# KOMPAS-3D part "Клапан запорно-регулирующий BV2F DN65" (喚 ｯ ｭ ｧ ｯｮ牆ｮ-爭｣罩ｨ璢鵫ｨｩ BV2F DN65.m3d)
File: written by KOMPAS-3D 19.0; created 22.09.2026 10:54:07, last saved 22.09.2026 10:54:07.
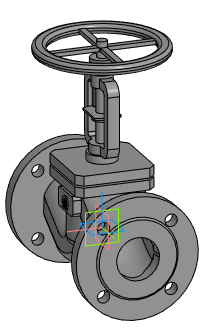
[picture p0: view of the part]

Document properties: Автор: Энергия; Полное имя файла: Z:\3.Личные\sachek\Dendor\_3D для проектировщиков\5.7 Клапан запорно-регулирующий BV2F\BV2F_STP\Клапан запорно-регулирующий BV2F DN65.m3d

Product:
- Part/product: Клапан запорно-регулирующий BV2F DN65

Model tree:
1. Операция без истории:1  (labels: Клапан запорно-регулирующий BV2F DN65)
